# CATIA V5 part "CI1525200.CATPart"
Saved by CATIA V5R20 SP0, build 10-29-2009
Part number: CI1525200
Bounding box of the stored display mesh (mm): x -24 to 24, y -19.758 to 234.5, z -29.741 to 27.753
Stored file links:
  C:\Users\Raffaele\Desktop\3D X SITO CF\BOLEX\19-INCLINED ASSEMBLY REF_CI\CI1525200.CATPart

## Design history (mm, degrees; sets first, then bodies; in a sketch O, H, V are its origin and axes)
Set1
  DatumSurface1 to DatumSurface16 "MANIFOLD_SOLID_BREP #393"
  DatumSurface17 to DatumSurface39 "MANIFOLD_SOLID_BREP #1138"
Body1 (main body)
